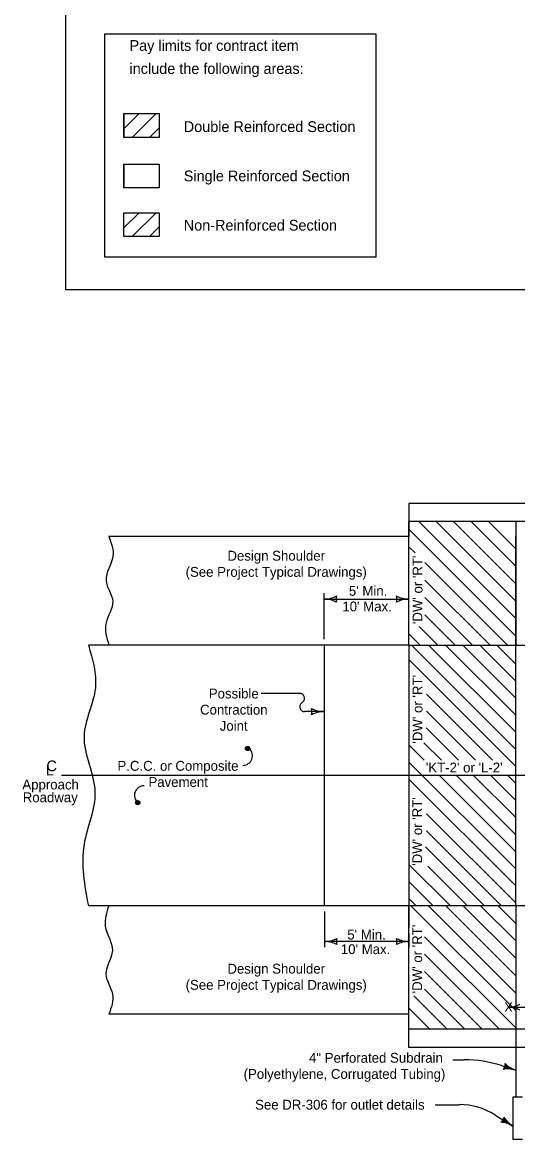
# Model space of a CAD drawing. Extents: x 10045 to 81668, y 6370 to 11018.
# Drawn here: x 17259 to 18102, y 6476 to 8380 of the extents above; entities that cross this region are included whole.
import ezdxf

# ---------------------------------------------------------------- set-up
doc = ezdxf.new("R2010")
doc.units = 0
for name, color, linetype in [('Alignment', 7, 'Continuous'), ('Default', 7, 'Continuous'), ('dsnStdLineWork', 7, 'Continuous'), ('Level 5', 7, 'Continuous')]:
    doc.layers.add(name, color=color, linetype=linetype)

msp = doc.modelspace()

# ---------------------------------------------------------------- linework, layer by layer
at = {"layer": 'Alignment'}
for p, q in [((17431.6, 8224.3), (17491.3, 8224.3)), ((17431.6, 8183.8), (17431.6, 8224.3)), ((17491.3, 8224.3), (17491.3, 8183.8)), ((17491.3, 8183.8), (17431.6, 8183.8)), ((17431.6, 8138.2), (17491.3, 8138.2)), ((17431.6, 8097.8), (17431.6, 8138.2)), ((17491.3, 8138.2), (17491.3, 8097.8)), ((17491.3, 8097.8), (17431.6, 8097.8)), ((17772.2, 7329), (17772.2, 7407.4)), ((17916.7, 7366), (17916.7, 7407.4)), ((17772.2, 7397.2), (17916.7, 7397.2)), ((17916.7, 7318.7), (17916.7, 6874.6)), ((17730.9, 7236.4), (17665.3, 7236.4)), ((17735.1, 7220.9), (17736.3, 7222)), ((17772, 7205.3), (17739.2, 7205.3)), ((17546.6, 7096.7), (17546.6, 7096.7)), ((19281.1, 6874.6), (17916.7, 6874.6)), ((17773.2, 6865), (17773.2, 6804.1)), ((17916.7, 6828), (17916.7, 6804.1)), ((17916.7, 6813.7), (17773.2, 6813.7)), ((18085.8, 6701.9), (18117.1, 6701.9)), ((17991.4, 6612.2), (18011, 6612.2)), ((17961.3, 6535.6), (18002.9, 6535.6)), ((18062.9, 6518.4), (18093.5, 6499.2))]:
    msp.add_line(p, q, dxfattribs=at)
for centre, radius, start, end in [((17730.9, 7228.2), 8.22, 311.3092, 90), ((17739.2, 7213.6), 8.22, 131.309, 270), ((17634, 7130.2), 16.4, 270, 48.6908), ((17465.9, 7062.7), 16.4, 90, 228.691), ((18011, 6406.6), 205.6, 72.1406, 90), ((18002.9, 6422.6), 113.1, 57.9168, 90)]:
    msp.add_arc(centre, radius, start, end, dxfattribs=at)
at = {"layer": 'Default'}
msp.add_line((18841.9, 7529.2), (17916.7, 7529.2), dxfattribs=at)
at = {"layer": 'dsnStdLineWork'}
for p, q in [((17431.6, 8224.3), (17491.3, 8224.3)), ((17431.6, 8224.3), (17431.6, 8183.8)), ((17431.6, 8198.7), (17457.3, 8224.3)), ((17445.9, 8183.8), (17486.4, 8224.3)), ((17491.3, 8224.3), (17491.3, 8183.8)), ((17475, 8183.8), (17491.3, 8200.2)), ((17491.3, 8183.8), (17431.6, 8183.8)), ((17431.6, 8138.2), (17491.3, 8138.2)), ((17431.6, 8138.2), (17431.6, 8097.8)), ((17491.3, 8138.2), (17491.3, 8097.8)), ((17491.3, 8097.8), (17431.6, 8097.8)), ((17431.6, 8029.6), (17457.3, 8055.3)), ((17445.9, 8014.8), (17486.4, 8055.3)), ((17475, 8014.8), (17491.3, 8031.2)), ((18804.9, 7560), (17916.7, 7560)), ((17916.7, 7560), (17916.7, 7503.7)), ((17916.7, 7318.7), (17916.7, 7529.2)), ((18098.7, 7363.9), (17933.4, 7529.2)), ((18098.7, 7393.6), (17963.1, 7529.2)), ((18098.7, 7423.3), (17992.8, 7529.2)), ((18098.7, 7453), (18022.5, 7529.2)), ((18098.7, 7482.7), (18052.2, 7529.2)), ((18098.7, 7529.2), (18098.7, 7318.7)), ((17916.7, 7503.7), (17405.9, 7503.7)), ((18098.7, 7334.2), (17916.7, 7516.1)), ((17916.7, 7318.7), (17916.7, 7503.7)), ((18098.7, 7318.7), (18098.7, 7503.7)), ((17927.4, 7475.8), (17916.7, 7486.4)), ((18084.5, 7318.7), (17943.8, 7459.3)), ((18054.8, 7318.7), (17943.8, 7429.6)), ((18025.1, 7318.7), (17943.8, 7399.9)), ((17995.4, 7318.7), (17943.8, 7370.2)), ((17916.7, 7318.7), (17916.7, 7355.7)), ((17965.7, 7318.7), (17933.9, 7350.4)), ((17936, 7318.7), (17916.7, 7337.9)), ((17916.7, 7318.7), (17371.1, 7318.7)), ((17772.2, 7318.7), (17772.2, 6874.6)), ((17916.7, 7318.7), (19327.8, 7318.7)), ((18098.7, 7141.1), (17921.1, 7318.7)), ((18098.7, 7170.2), (17950.2, 7318.7)), ((18098.7, 7199.3), (17979.2, 7318.7)), ((18098.7, 7228.3), (18008.3, 7318.7)), ((18098.7, 7257.4), (18037.4, 7318.7)), ((18098.7, 7286.5), (18066.5, 7318.7)), ((18098.7, 6874.6), (18098.7, 7318.7)), ((18098.7, 7112), (17916.7, 7294)), ((18059.1, 7122.5), (17946.7, 7235)), ((17733.8, 7219.7), (17735.1, 7220.9)), ((18030.1, 7122.5), (17946.4, 7206.2)), ((18001, 7122.5), (17945.9, 7177.5)), ((17942.8, 7122.5), (17916.7, 7148.6)), ((17971.9, 7122.5), (17942.3, 7152.1)), ((18098.7, 6937.6), (17916.7, 7119.5)), ((18841.9, 7096.7), (17325.6, 7096.7)), ((18098.7, 6908.5), (17916.7, 7090.5)), ((18098.7, 6966.7), (17968.7, 7096.7)), ((18098.7, 6995.7), (17997.7, 7096.7)), ((18098.7, 7024.8), (18026.8, 7096.7)), ((18098.7, 7053.9), (18055.9, 7096.7)), ((18098.7, 7083), (18085, 7096.7)), ((18098.7, 6879.4), (17946.7, 7031.4)), ((18074.4, 6874.6), (17946.9, 7002.1)), ((18045.3, 6874.6), (17945.2, 6974.7)), ((17987.2, 6874.6), (17916.7, 6945.1)), ((18016.3, 6874.6), (17948.9, 6942)), ((17958.1, 6874.6), (17916.7, 6916)), ((17916.7, 6874.6), (17371.1, 6874.6)), ((17929, 6874.6), (17916.7, 6886.9)), ((17916.7, 6874.6), (17916.7, 6837.6)), ((17916.7, 6689.6), (17916.7, 6874.6)), ((17916.7, 6664.1), (17916.7, 6874.6)), ((18098.7, 6696), (17920.1, 6874.6)), ((18098.7, 6725.7), (17949.8, 6874.6)), ((18098.7, 6755.4), (17979.4, 6874.6)), ((18098.7, 6785.1), (18009.1, 6874.6)), ((18098.7, 6814.8), (18038.8, 6874.6)), ((18098.7, 6844.5), (18068.5, 6874.6)), ((18098.7, 6874.2), (18098.2, 6874.6)), ((18098.7, 6874.6), (18098.7, 6664.1)), ((18098.7, 6666.3), (17943.2, 6821.8)), ((18071.1, 6664.1), (17943.2, 6792.1)), ((18041.4, 6664.1), (17943.2, 6762.4)), ((17982, 6664.1), (17924.8, 6721.3)), ((18011.7, 6664.1), (17943.2, 6732.7)), ((17916.7, 6689.6), (17405.9, 6689.6)), ((17952.3, 6664.1), (17916.7, 6699.8)), ((17916.7, 6633.3), (17916.7, 6689.6)), ((18841.9, 6664.1), (17916.7, 6664.1)), ((18098.7, 6664.1), (18098.7, 6548.4)), ((18804.9, 6633.3), (17916.7, 6633.3)), ((18074.1, 6602.3), (18098.7, 6594.4)), ((18098.7, 6594.4), (18079.9, 6600.5)), ((18110, 6548.4), (18093.5, 6548.4)), ((18093.5, 6548.4), (18093.5, 6476)), ((18093.5, 6499.2), (18076.8, 6509.7)), ((18110, 6476), (18093.5, 6476))]:
    msp.add_line(p, q, dxfattribs=at)
for points in [[(17398.9, 8360.3), (17860.1, 8360.3), (17860.1, 7980), (17398.9, 7980)], [(17431.6, 8055.3), (17491.3, 8055.3), (17491.3, 8014.8), (17431.6, 8014.8)]]:
    msp.add_lwpolyline(points, close=True, dxfattribs=at)
for points in [[(18098.7, 7318.7), (18098.7, 7318.7)], [(17642.4, 7139.3), (17641.2, 7139.8), (17639.3, 7140.4), (17638.9, 7142.3), (17639.2, 7144), (17640.4, 7145.6), (17642.2, 7145.4), (17644.1, 7145.2), (17645, 7143.6), (17645.2, 7142), (17644, 7140), (17642.7, 7139.8), (17640.8, 7140.3), (17639.2, 7141.5), (17639.3, 7143.3), (17640.5, 7144.7), (17642.2, 7144.9), (17644.1, 7144.5), (17644.4, 7143.5), (17644.7, 7142.2), (17643.8, 7140.6), (17642.5, 7140.7), (17640.9, 7140.9), (17639.7, 7141.8), (17640.3, 7143.4), (17641.5, 7144.3), (17643.1, 7144.3), (17643.5, 7143.5), (17644, 7142.5), (17643.2, 7141.3), (17642.1, 7141), (17641, 7141.5), (17640.9, 7142.7), (17641.5, 7143.5), (17642.6, 7143.8), (17643.1, 7143.4), (17643.4, 7142.7), (17642.8, 7141.8), (17642.1, 7141.6), (17641.3, 7142.1), (17641.5, 7142.7), (17642, 7143.1), (17642.7, 7143.1), (17642.7, 7142.5), (17642.1, 7142.2)], [(17455.3, 7047), (17454.1, 7047.6), (17452.2, 7048.2), (17451.9, 7050.1), (17452.1, 7051.8), (17453.3, 7053.3), (17455.1, 7053.2), (17457, 7052.9), (17457.9, 7051.4), (17458.1, 7049.8), (17457, 7047.7), (17455.6, 7047.5), (17453.7, 7048), (17452.2, 7049.2), (17452.2, 7051), (17453.4, 7052.5), (17455.1, 7052.6), (17457, 7052.3), (17457.3, 7051.2), (17457.7, 7049.9), (17456.8, 7048.3), (17455.4, 7048.4), (17453.8, 7048.6), (17452.7, 7049.5), (17453.3, 7051.1), (17454.5, 7052), (17456, 7052.1), (17456.4, 7051.2), (17456.9, 7050.2), (17456.2, 7049), (17455, 7048.7), (17454, 7049.3), (17453.9, 7050.4), (17454.4, 7051.3), (17455.5, 7051.6), (17456, 7051.1), (17456.3, 7050.5), (17455.8, 7049.5), (17455, 7049.4), (17454.3, 7049.8), (17454.4, 7050.4), (17455, 7050.8), (17455.7, 7050.8), (17455.7, 7050.3), (17455, 7050)], [(18079.1, 6596.9), (18080.9, 6600.1), (18081.3, 6603.9), (18084.9, 6600.5), (18091.1, 6596.9), (18083.4, 6597.5), (18079.8, 6597.1), (18081.6, 6599.9), (18082, 6602.3), (18084.4, 6600.1), (18087.8, 6597.9), (18083.5, 6598.1), (18081.2, 6598), (18082.5, 6600.9), (18084.9, 6598.9), (18082.5, 6598.9), (18082.8, 6599.9), (18083.7, 6599.3)], [(18075.2, 6506.4), (18077.8, 6509.1), (18079.1, 6512.6), (18081.7, 6508.5), (18086.8, 6503.4), (18079.5, 6506), (18075.9, 6506.4), (18078.3, 6508.7), (18079.3, 6510.9), (18081.1, 6508.2), (18083.8, 6505.3), (18079.7, 6506.5), (18077.5, 6507), (18079.5, 6509.4), (18081.3, 6506.9), (18079, 6507.5), (18079.5, 6508.4), (18080.2, 6507.6)]]:
    msp.add_lwpolyline(points, dxfattribs=at)
for centre in [(17642.1, 7142.6), (17455.1, 7050.3)]:
    msp.add_circle(centre, 3.6, dxfattribs=at)
for centre, radius, start, end in [((17772.2, 7441.5), 44.4, 270, 298.0725), ((17772.2, 7352.8), 44.4, 61.9275, 90), ((17809.5, 7397.2), 17.1, 162.2666, 197.7334), ((17879.5, 7397.2), 17.1, 342.2667, 17.7334), ((17916.7, 7441.5), 44.4, 241.9275, 270), ((17916.7, 7352.8), 44.4, 90, 118.0725), ((17734.8, 7205.3), 17.1, 342.2667, 17.7334), ((17772, 7249.7), 44.4, 241.9275, 270), ((17772, 7161), 44.4, 90, 118.0725), ((17773.2, 6858.3), 44.6, 270, 298.0725), ((17810.6, 6813.7), 17.2, 162.2666, 197.7334), ((17879.3, 6813.7), 17.2, 342.2667, 17.7334), ((17916.7, 6858.3), 44.6, 241.9275, 270), ((17879.3, 6813.7), 17.2, 342.2667, 17.7334), ((17916.7, 6858.3), 44.6, 241.9275, 270), ((17773.2, 6769.1), 44.6, 61.9275, 90), ((17916.7, 6769.1), 44.6, 90, 118.0725), ((17916.7, 6769.1), 44.6, 90, 118.0725), ((18085.8, 6744.2), 42.3, 270, 298.0725), ((18085.8, 6659.6), 42.3, 61.9275, 90), ((18063.8, 6605.6), 16.9, 324.4082, 359.8749), ((18085.3, 6552.8), 43.7, 72.1415, 100.214), ((18112.1, 6636), 43.7, 224.0691, 252.1415), ((18062.5, 6518.7), 16.9, 310.1825, 345.6492), ((18116.7, 6536.2), 43.7, 209.8434, 237.9159), ((18070.3, 6462.2), 43.7, 57.9159, 85.9884)]:
    msp.add_arc(centre, radius, start, end, dxfattribs=at)
for points in [[(17405.9, 7503.7), (17412.8, 7469.5), (17401.1, 7428.8), (17412.5, 7393.3), (17401.1, 7356.7), (17405.9, 7318.7)], [(17371.1, 7318.7), (17383, 7246), (17363.7, 7163.4), (17382.2, 7068.5), (17363.7, 6979), (17371.1, 6874.6)], [(17405.9, 6874.6), (17399.9, 6839.9), (17411.9, 6798.1), (17400.9, 6758.3), (17412.2, 6723.9), (17405.9, 6689.6)]]:
    msp.add_spline(points, degree=3, dxfattribs=at)
at = {"layer": 'Level 5'}
msp.add_lwpolyline([(17332.5, 9944), (20467.5, 9944), (20467.5, 7924), (17332.5, 7924)], close=True, dxfattribs=at)

# ---------------------------------------------------------------- texts
at = {"layer": 'Alignment'}
for s, height, p in [('Pay limits for contract item', 18.375, (17441.1, 8331.3)), ('include the following areas:', 18.375, (17441.1, 8292)), ('Double Reinforced Section', 18.375, (17533.4, 8193)), ('Single Reinforced Section', 18.375, (17533.4, 8109)), ('Non-Reinforced Section', 18.375, (17533.4, 8025)), ('Design Shoulder', 16.8, (17607.8, 7462.6)), ('(See Project Typical Drawings)', 16.8, (17536.6, 7435.1)), ("5' Min.", 16.8, (17814.5, 7402.8)), ("10' Max.", 16.8, (17803.4, 7376.2)), ('Possible', 16.8, (17576.1, 7227.8)), ('Contraction', 16.8, (17561.2, 7200.3)), ('Joint', 16.8, (17594.7, 7172.8)), ('C', 18.4, (17299.8, 7103.8)), ('P.C.C. or Composite', 16.8, (17420.6, 7104.6)), ('L', 18.4, (17298.7, 7096.6)), ("'KT-2' or 'L-2'", 16.8, (17945.4, 7101.7)), ('Approach', 16.8, (17258.7, 7072.8)), ('Pavement', 16.8, (17473.4, 7077.1)), ('Roadway', 16.8, (17259.4, 7050.9)), ("5' Min.", 16.8, (17811.8, 6817)), ("10' Max.", 16.8, (17800.8, 6792.2)), ('Design Shoulder', 16.8, (17607.8, 6758.9)), ('(See Project Typical Drawings)', 16.8, (17536.6, 6731.4)), ('X', 16, (18079, 6693.9)), ('4" Perforated Subdrain ', 16.8, (17746.7, 6607.1)), ('(Polyethylene, Corrugated Tubing)', 16.8, (17635.3, 6579.6)), ('See DR-306 for outlet details', 16.8, (17654.9, 6527.2))]:
    msp.add_text(s, height=height, dxfattribs=at).set_placement(p)
for p in [(17939.8, 7354.4), (17939.8, 7150.8), (17939.2, 6942.6), (17939.2, 6725.3)]:
    msp.add_text("'DW' or 'RT'", height=16.8, rotation=90, dxfattribs=at).set_placement(p)

doc.saveas('drawing.dxf')
